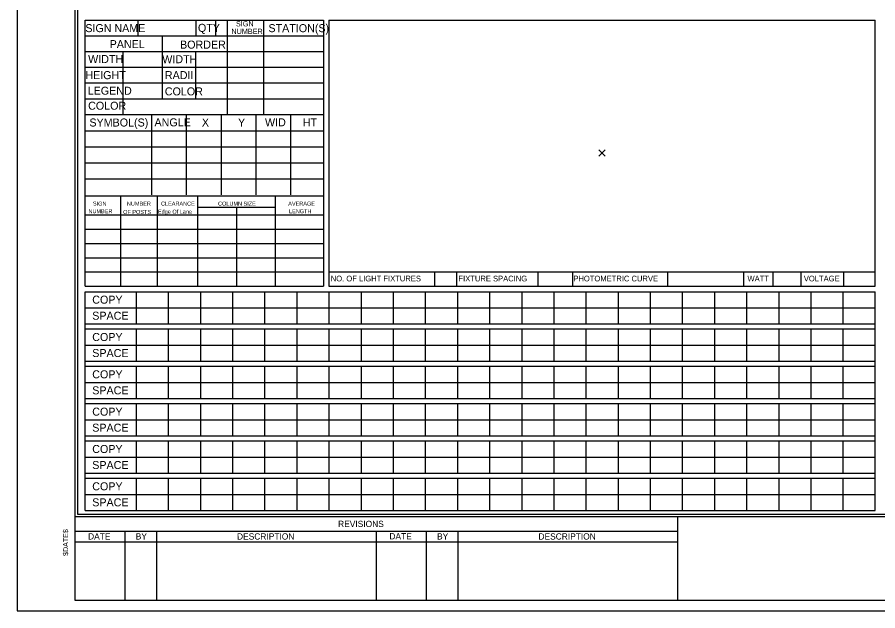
# Model space of a CAD drawing. Extents: x 121688 to 126625, y -22764 to -19972.
# Drawn here: x 125073 to 125847, y -22752 to -22218 of the extents above; entities that cross this region are included whole.
import ezdxf

# ---------------------------------------------------------------- set-up
doc = ezdxf.new("R2010")
doc.units = 0
for name, color, linetype in [('NonPlottingEle_dp', 7, 'Continuous'), ('PlotBorder_dp', 7, 'Continuous'), ('SheetBorder_dp', 7, 'Continuous'), ('SheetLines_dp', 7, 'Continuous'), ('SheetLinesMisc2_dp', 7, 'Continuous'), ('TextMinor', 7, 'Continuous'), ('TextMisc', 7, 'Continuous')]:
    doc.layers.add(name, color=color, linetype=linetype)

msp = doc.modelspace()

# ---------------------------------------------------------------- linework, layer by layer
at = {"layer": 'NonPlottingEle_dp'}
for p, q in [((125595.73, -22337.17), (125601.33, -22342.77)), ((125595.73, -22342.77), (125601.33, -22337.17))]:
    msp.add_line(p, q, dxfattribs=at)
at = {"layer": 'PlotBorder_dp'}
msp.add_lwpolyline([(125072.61, -22751.63), (126625.18, -22751.63), (126625.18, -21754.22), (125072.61, -21754.22)], close=True, dxfattribs=at)
at = {"layer": 'SheetBorder_dp'}
for p, q in [((125124.37, -21763.63), (125124.37, -22742.22)), ((125124.37, -22666.94), (126573.42, -22666.94)), ((125124.37, -22742.22), (126573.42, -22742.22))]:
    msp.add_line(p, q, dxfattribs=at)
at = {"layer": 'SheetLines_dp'}
for p, q in [((125666.35, -22666.94), (125666.35, -22742.22)), ((125124.37, -22680.11), (125666.35, -22680.11)), ((125169.53, -22680.11), (125169.53, -22742.22)), ((125197.76, -22680.11), (125197.76, -22742.22)), ((125395.36, -22680.11), (125395.36, -22742.22)), ((125440.52, -22680.11), (125440.52, -22742.22)), ((125468.75, -22680.11), (125468.75, -22742.22)), ((125124.37, -22689.52), (125666.35, -22689.52))]:
    msp.add_line(p, q, dxfattribs=at)
at = {"layer": 'SheetLinesMisc2_dp'}
for p, q in [((125126.93, -21765.86), (125126.93, -22664.86)), ((125133.86, -22459.77), (125133.86, -22220.52)), ((125133.86, -22220.52), (125348, -22220.52)), ((125181.06, -22220.52), (125181.06, -22234.65)), ((125233.11, -22220.52), (125233.11, -22234.65)), ((125250.9, -22220.52), (125250.9, -22234.65)), ((125261.49, -22220.52), (125261.49, -22305.31)), ((125294.08, -22220.52), (125294.08, -22305.31)), ((125348, -22220.52), (125348, -22459.77)), ((125352.94, -22220.52), (125844.12, -22220.52)), ((125352.94, -22220.52), (125352.94, -22459.43)), ((125844.12, -22459.43), (125844.12, -22220.5)), ((125133.86, -22234.65), (125348, -22234.65)), ((125203.07, -22234.65), (125203.07, -22291.33)), ((125133.86, -22248.78), (125348, -22248.78)), ((125167.7, -22248.78), (125167.7, -22305.31)), ((125232.93, -22248.93), (125232.93, -22291.33)), ((125133.86, -22262.92), (125348, -22262.92)), ((125133.86, -22277.05), (125348, -22277.05)), ((125133.86, -22291.18), (125213.28, -22291.18)), ((125203.07, -22291.33), (125261.49, -22291.33)), ((125261.49, -22291.18), (125348, -22291.18)), ((125133.86, -22305.31), (125348, -22305.31)), ((125193.33, -22305.59), (125193.33, -22377.74)), ((125224.62, -22305.59), (125224.62, -22377.74)), ((125255.91, -22305.59), (125255.91, -22377.74)), ((125287.19, -22305.59), (125287.19, -22377.74)), ((125318.48, -22305.59), (125318.48, -22377.74)), ((125133.91, -22320.02), (125348, -22320.02)), ((125133.91, -22334.45), (125348, -22334.45)), ((125133.91, -22348.88), (125348, -22348.88)), ((125133.91, -22363.31), (125348, -22363.31)), ((125133.86, -22378.43), (125348, -22378.43)), ((125165.63, -22378.43), (125165.63, -22459.77)), ((125198.48, -22378.43), (125198.48, -22459.77)), ((125234.74, -22378.43), (125234.74, -22459.77)), ((125304.58, -22378.43), (125304.58, -22459.77)), ((125234.74, -22388.78), (125304.53, -22388.78)), ((125269.8, -22388.78), (125269.8, -22459.77)), ((125133.86, -22395.68), (125348, -22395.68)), ((125133.86, -22408.5), (125348, -22408.5)), ((125133.86, -22421.32), (125348, -22421.32)), ((125133.86, -22434.14), (125348, -22434.14)), ((125133.86, -22446.96), (125348, -22446.96)), ((125352.94, -22446.95), (125844.12, -22446.95)), ((125447.81, -22446.95), (125447.81, -22459.77)), ((125467.69, -22446.95), (125467.69, -22459.77)), ((125540.83, -22446.95), (125540.83, -22459.77)), ((125571.96, -22446.95), (125571.96, -22459.77)), ((125657.48, -22446.95), (125657.48, -22459.77)), ((125725.74, -22446.95), (125725.74, -22459.77)), ((125752.09, -22446.95), (125752.09, -22459.77)), ((125777.5, -22446.95), (125777.5, -22459.77)), ((125815.76, -22446.95), (125815.76, -22459.77)), ((125133.86, -22459.77), (125348, -22459.77)), ((125352.94, -22459.43), (125352.94, -22459.75)), ((125352.94, -22459.77), (125844.12, -22459.77)), ((125844.12, -22459.75), (125844.12, -22459.43)), ((125133.86, -22464.7), (125844.12, -22464.7)), ((125133.86, -22661.36), (125133.86, -22464.7)), ((125179.58, -22464.7), (125179.58, -22493.55)), ((125208.48, -22464.7), (125208.48, -22493.55)), ((125237.37, -22464.7), (125237.37, -22493.55)), ((125266.26, -22464.7), (125266.26, -22493.55)), ((125295.15, -22464.7), (125295.15, -22493.55)), ((125324.04, -22464.7), (125324.04, -22493.55)), ((125352.94, -22464.7), (125352.94, -22493.55)), ((125381.83, -22464.7), (125381.83, -22493.55)), ((125410.72, -22464.7), (125410.72, -22493.55)), ((125439.61, -22464.7), (125439.61, -22493.55)), ((125468.51, -22464.7), (125468.51, -22493.55)), ((125497.4, -22464.7), (125497.4, -22493.55)), ((125526.3, -22464.7), (125526.3, -22493.55)), ((125555.19, -22464.7), (125555.19, -22493.55)), ((125584.09, -22464.7), (125584.09, -22493.55)), ((125612.98, -22464.7), (125612.98, -22493.55)), ((125641.87, -22464.7), (125641.87, -22493.55)), ((125670.76, -22464.7), (125670.76, -22493.55)), ((125699.66, -22464.7), (125699.66, -22493.55)), ((125728.55, -22464.7), (125728.55, -22493.55)), ((125757.44, -22464.7), (125757.44, -22493.55)), ((125786.33, -22464.7), (125786.33, -22493.55)), ((125815.23, -22464.7), (125815.23, -22493.55)), ((125844.12, -22661.36), (125844.12, -22464.7)), ((125133.86, -22479.12), (125844.12, -22479.12)), ((125133.86, -22493.55), (125844.12, -22493.55)), ((125133.86, -22498.26), (125844.12, -22498.26)), ((125179.58, -22498.26), (125179.58, -22527.12)), ((125208.48, -22498.26), (125208.48, -22527.12)), ((125237.37, -22498.26), (125237.37, -22527.12)), ((125266.26, -22498.26), (125266.26, -22527.12)), ((125295.15, -22498.26), (125295.15, -22527.12)), ((125324.04, -22498.26), (125324.04, -22527.12)), ((125352.94, -22498.26), (125352.94, -22527.12)), ((125381.83, -22498.26), (125381.83, -22527.12)), ((125410.72, -22498.26), (125410.72, -22527.12)), ((125439.61, -22498.26), (125439.61, -22527.12)), ((125468.51, -22498.26), (125468.51, -22527.12)), ((125497.4, -22498.26), (125497.4, -22527.12)), ((125526.3, -22498.26), (125526.3, -22527.12)), ((125555.19, -22498.26), (125555.19, -22527.12)), ((125584.09, -22498.26), (125584.09, -22527.12)), ((125612.98, -22498.26), (125612.98, -22527.12)), ((125641.87, -22498.26), (125641.87, -22527.12)), ((125670.76, -22498.26), (125670.76, -22527.12)), ((125699.66, -22498.26), (125699.66, -22527.12)), ((125728.55, -22498.26), (125728.55, -22527.12)), ((125757.44, -22498.26), (125757.44, -22527.12)), ((125786.33, -22498.26), (125786.33, -22527.12)), ((125815.23, -22498.26), (125815.23, -22527.12)), ((125133.86, -22512.69), (125844.12, -22512.69)), ((125133.86, -22527.12), (125844.12, -22527.12)), ((125133.86, -22531.82), (125844.12, -22531.82)), ((125179.58, -22531.82), (125179.58, -22560.68)), ((125208.48, -22531.82), (125208.48, -22560.68)), ((125237.37, -22531.82), (125237.37, -22560.68)), ((125266.26, -22531.82), (125266.26, -22560.68)), ((125295.15, -22531.82), (125295.15, -22560.68)), ((125324.04, -22531.82), (125324.04, -22560.68)), ((125352.94, -22531.82), (125352.94, -22560.68)), ((125381.83, -22531.82), (125381.83, -22560.68)), ((125410.72, -22531.82), (125410.72, -22560.68)), ((125439.61, -22531.82), (125439.61, -22560.68)), ((125468.51, -22531.82), (125468.51, -22560.68)), ((125497.4, -22531.82), (125497.4, -22560.68)), ((125526.3, -22531.82), (125526.3, -22560.68)), ((125555.19, -22531.82), (125555.19, -22560.68)), ((125584.09, -22531.82), (125584.09, -22560.68)), ((125612.98, -22531.82), (125612.98, -22560.68)), ((125641.87, -22531.82), (125641.87, -22560.68)), ((125670.76, -22531.82), (125670.76, -22560.68)), ((125699.66, -22531.82), (125699.66, -22560.68)), ((125728.55, -22531.82), (125728.55, -22560.68)), ((125757.44, -22531.82), (125757.44, -22560.68)), ((125786.33, -22531.82), (125786.33, -22560.68)), ((125815.23, -22531.82), (125815.23, -22560.68)), ((125133.86, -22546.25), (125844.12, -22546.25)), ((125133.86, -22560.68), (125844.12, -22560.68)), ((125133.86, -22565.38), (125844.12, -22565.38)), ((125179.58, -22565.38), (125179.58, -22594.24)), ((125208.48, -22565.38), (125208.48, -22594.24)), ((125237.37, -22565.38), (125237.37, -22594.24)), ((125266.26, -22565.38), (125266.26, -22594.24)), ((125295.15, -22565.38), (125295.15, -22594.24)), ((125324.04, -22565.38), (125324.04, -22594.24)), ((125352.94, -22565.38), (125352.94, -22594.24)), ((125381.83, -22565.38), (125381.83, -22594.24)), ((125410.72, -22565.38), (125410.72, -22594.24)), ((125439.61, -22565.38), (125439.61, -22594.24)), ((125468.51, -22565.38), (125468.51, -22594.24)), ((125497.4, -22565.38), (125497.4, -22594.24)), ((125526.3, -22565.38), (125526.3, -22594.24)), ((125555.19, -22565.38), (125555.19, -22594.24)), ((125584.09, -22565.38), (125584.09, -22594.24)), ((125612.98, -22565.38), (125612.98, -22594.24)), ((125641.87, -22565.38), (125641.87, -22594.24)), ((125670.76, -22565.38), (125670.76, -22594.24)), ((125699.66, -22565.38), (125699.66, -22594.24)), ((125728.55, -22565.38), (125728.55, -22594.24)), ((125757.44, -22565.38), (125757.44, -22594.24)), ((125786.33, -22565.38), (125786.33, -22594.24)), ((125815.23, -22565.38), (125815.23, -22594.24)), ((125133.86, -22579.8), (125844.12, -22579.8)), ((125133.86, -22594.24), (125844.12, -22594.24)), ((125133.86, -22598.95), (125844.12, -22598.95)), ((125179.58, -22598.95), (125179.58, -22627.8)), ((125208.48, -22598.95), (125208.48, -22627.8)), ((125237.37, -22598.95), (125237.37, -22627.8)), ((125266.26, -22598.95), (125266.26, -22627.8)), ((125295.15, -22598.95), (125295.15, -22627.8)), ((125324.04, -22598.95), (125324.04, -22627.8)), ((125352.94, -22598.95), (125352.94, -22627.8)), ((125381.83, -22598.95), (125381.83, -22627.8)), ((125410.72, -22598.95), (125410.72, -22627.8)), ((125439.61, -22598.95), (125439.61, -22627.8)), ((125468.51, -22598.95), (125468.51, -22627.8)), ((125497.4, -22598.95), (125497.4, -22627.8)), ((125526.3, -22598.95), (125526.3, -22627.8)), ((125555.19, -22598.95), (125555.19, -22627.8)), ((125584.09, -22598.95), (125584.09, -22627.8)), ((125612.98, -22598.95), (125612.98, -22627.8)), ((125641.87, -22598.95), (125641.87, -22627.8)), ((125670.76, -22598.95), (125670.76, -22627.8)), ((125699.66, -22598.95), (125699.66, -22627.8)), ((125728.55, -22598.95), (125728.55, -22627.8)), ((125757.44, -22598.95), (125757.44, -22627.8)), ((125786.33, -22598.95), (125786.33, -22627.8)), ((125815.23, -22598.95), (125815.23, -22627.8)), ((125133.86, -22613.38), (125844.12, -22613.38)), ((125133.86, -22627.8), (125844.12, -22627.8)), ((125133.86, -22632.51), (125844.12, -22632.51)), ((125179.58, -22632.51), (125179.58, -22661.36)), ((125208.48, -22632.51), (125208.48, -22661.36)), ((125237.37, -22632.51), (125237.37, -22661.36)), ((125266.26, -22632.51), (125266.26, -22661.36)), ((125295.15, -22632.51), (125295.15, -22661.36)), ((125324.04, -22632.51), (125324.04, -22661.36)), ((125352.94, -22632.51), (125352.94, -22661.36)), ((125381.83, -22632.51), (125381.83, -22661.36)), ((125410.72, -22632.51), (125410.72, -22661.36)), ((125439.61, -22632.51), (125439.61, -22661.36)), ((125468.51, -22632.51), (125468.51, -22661.36)), ((125497.4, -22632.51), (125497.4, -22661.36)), ((125526.3, -22632.51), (125526.3, -22661.36)), ((125555.19, -22632.51), (125555.19, -22661.36)), ((125584.09, -22632.51), (125584.09, -22661.36)), ((125612.98, -22632.51), (125612.98, -22661.36)), ((125641.87, -22632.51), (125641.87, -22661.36)), ((125670.76, -22632.51), (125670.76, -22661.36)), ((125699.66, -22632.51), (125699.66, -22661.36)), ((125728.55, -22632.51), (125728.55, -22661.36)), ((125757.44, -22632.51), (125757.44, -22661.36)), ((125786.33, -22632.51), (125786.33, -22661.36)), ((125815.23, -22632.51), (125815.23, -22661.36)), ((125133.86, -22646.94), (125844.12, -22646.94)), ((125133.86, -22661.36), (125844.12, -22661.36)), ((125126.93, -22664.86), (126571.13, -22664.86))]:
    msp.add_line(p, q, dxfattribs=at)

# ---------------------------------------------------------------- texts
at = {"layer": 'TextMinor'}
for s, height, p in [('SIGN NAME', 7.199, (125133.86, -22231.34)), ('QTY', 7.199, (125235.16, -22231.1)), ('SIGN', 4.705, (125269.36, -22226.18)), ('STATION(S)', 7.199, (125298.57, -22231.38)), ('NUMBER', 4.705, (125265.26, -22233.03)), ('PANEL', 7.199, (125155.75, -22245.7)), ('BORDER', 7.199, (125219.07, -22246.18)), ('WIDTH', 7.199, (125136.4, -22259.15)), ('WIDTH', 7.199, (125203.07, -22259.29)), ('HEIGHT', 7.199, (125133.86, -22273.63)), ('RADII', 7.199, (125205.43, -22273.61)), ('LEGEND', 7.199, (125136.03, -22287.61)), ('COLOR', 7.199, (125205.38, -22288.22)), ('COLOR', 7.199, (125136.4, -22301.1)), ('SYMBOL(S)', 7.199, (125137.55, -22316.2)), ('ANGLE', 7.199, (125196.08, -22316.05)), ('X', 7.2, (125238.7, -22316.2)), ('Y', 7.2, (125271.23, -22316.2)), ('WID', 7.199, (125295.46, -22316.05)), ('HT', 7.199, (125329.38, -22316.19)), ('NUMBER', 3.6, (125136.69, -22394.16)), ('SIGN', 3.6, (125140.72, -22387.31)), ('NUMBER', 3.6, (125171.29, -22387.36)), ('Edge Of Lane', 3.5997, (125199.16, -22394.58)), ('CLEARANCE', 3.6, (125201.94, -22387.33)), ('COLUMN SIZE', 3.5997, (125253.24, -22387.33)), ('AVERAGE', 3.6, (125316.37, -22387.33)), ('LENGTH', 3.6, (125317.05, -22394.16)), ('OF POSTS', 3.6, (125167.89, -22394.84)), ('NO. OF LIGHT FIXTURES', 5.102, (125354.59, -22455.47)), ('FIXTURE SPACING', 5.102, (125469.46, -22455.47)), ('PHOTOMETRIC CURVE', 5.102, (125572.77, -22455.47)), ('WATT', 5.102, (125729.4, -22455.47)), ('VOLTAGE', 5.102, (125780.05, -22455.47)), ('COPY', 7.199, (125140.09, -22475.48)), ('SPACE', 7.199, (125140.09, -22489.92)), ('COPY', 7.199, (125140.09, -22509.06)), ('SPACE', 7.199, (125140.09, -22523.49)), ('COPY', 7.199, (125140.09, -22542.61)), ('SPACE', 7.199, (125140.09, -22557.04)), ('COPY', 7.199, (125140.09, -22576.18)), ('SPACE', 7.199, (125140.09, -22590.6)), ('COPY', 7.199, (125140.09, -22609.75)), ('SPACE', 7.199, (125140.09, -22624.17)), ('COPY', 7.199, (125140.09, -22643.31)), ('SPACE', 7.199, (125140.09, -22657.73))]:
    msp.add_text(s, height=height, dxfattribs=at).set_placement(p)
msp.add_text('$DATE$', height=4.611, rotation=90, dxfattribs=at).set_placement((125118.43, -22702.3))
at = {"layer": 'TextMisc'}
for s, p in [('REVISIONS', (125361.2, -22676.35)), ('BY', (125179.22, -22687.55)), ('BY', (125450.22, -22687.55))]:
    msp.add_text(s, height=5.646, dxfattribs=at).set_placement(p)
for s, height, rotation, p in [('DATE', 5.646, 359.86925, (125136.32, -22687.55)), ('DESCRIPTION', 5.6446, 0.04975, (125270.31, -22687.64)), ('DATE', 5.646, 359.86925, (125407.31, -22687.45)), ('DESCRIPTION', 5.6446, 0.04975, (125541.39, -22687.64))]:
    msp.add_text(s, height=height, rotation=rotation, dxfattribs=at).set_placement(p)

doc.saveas('drawing.dxf')
